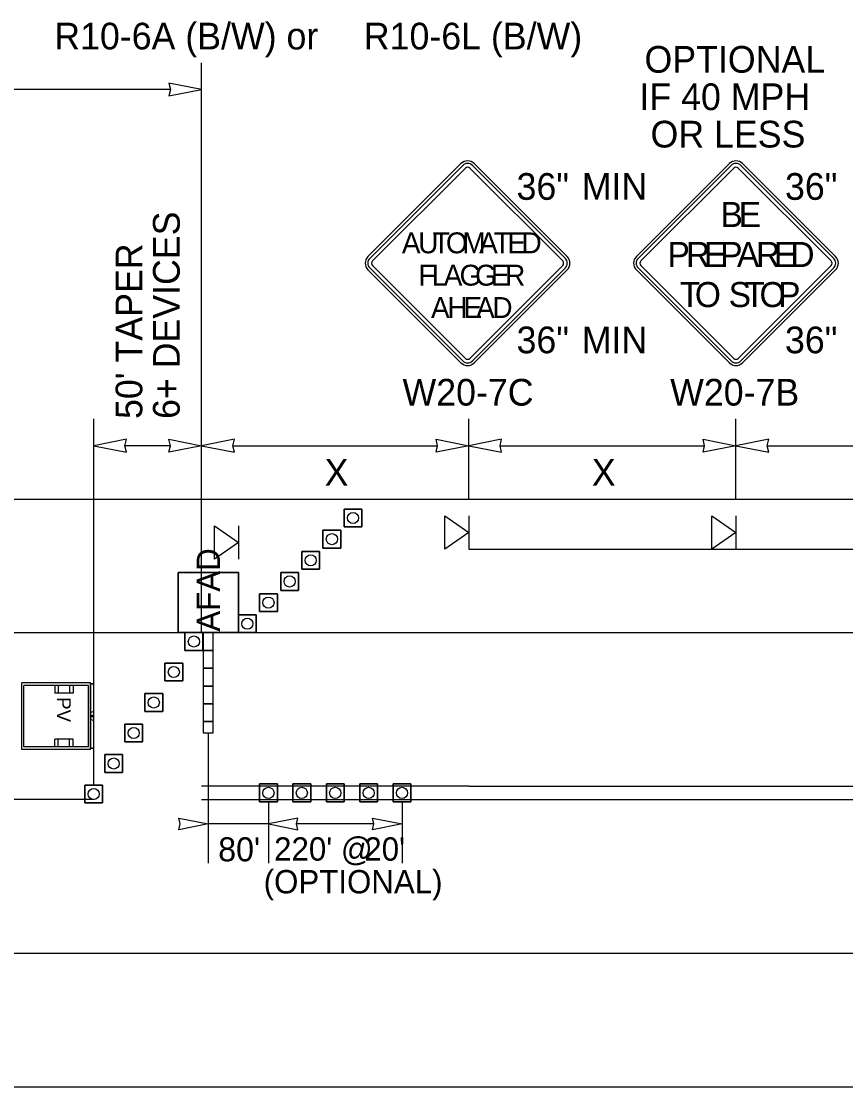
# Model space of a CAD drawing. Extents: x 99999.1 to 100095.7, y 99995 to 100010.7.
# Drawn here: x 100050.933 to 100053.402, y 100005.732 to 100008.923 of the extents above; entities that cross this region are included whole.
import ezdxf

# ---------------------------------------------------------------- set-up
doc = ezdxf.new("R2010")
doc.units = 0
for name, color, linetype in [('RD_ED_ShoulderPavedEdge', 7, 'Continuous'), ('RD_MK_LineDblYellowCenter', 7, 'Continuous'), ('RD_MK_LineEdgeWhite', 7, 'Continuous'), ('RD_MK_LineNoPass', 7, 'Continuous'), ('RD_MK_LineSkipCenter', 7, 'Continuous'), ('TR_SN_ConstructionSigns', 7, 'Continuous'), ('TR_WZ_AFAD', 7, 'Continuous'), ('TR_WZ_PortableSignMountBlk-Org', 7, 'Continuous'), ('TR_WZ_PortableSignMountBlk-Wht', 7, 'Continuous'), ('TR_WZ_ProtectiveVehicle', 7, 'Continuous'), ('TR_WZ_TrafficCone', 7, 'Continuous'), ('TR_WZ_WorkZoneDetails', 7, 'Continuous'), ('TR_WZ_WorkZoneTextCurrent', 7, 'Continuous')]:
    doc.layers.add(name, color=color, linetype=linetype)

msp = doc.modelspace()

# ---------------------------------------------------------------- linework, layer by layer
at = {"layer": 'RD_ED_ShoulderPavedEdge'}
for p, q in [((100040.1076, 100007.4923), (100055.6424, 100007.4923)), ((100040.1076, 100005.7323), (100055.6424, 100005.7323))]:
    msp.add_line(p, q, dxfattribs=at)
at = {"layer": 'RD_MK_LineDblYellowCenter'}
for p, q in [((100052.2733, 100006.6323), (100055.6631, 100006.6323)), ((100052.2733, 100006.5923), (100055.6218, 100006.5923))]:
    msp.add_line(p, q, dxfattribs=at)
at = {"layer": 'RD_MK_LineEdgeWhite'}
for p, q in [((100040.1076, 100007.0923), (100055.6424, 100007.0923)), ((100040.1076, 100006.1323), (100055.6424, 100006.1323))]:
    msp.add_line(p, q, dxfattribs=at)
at = {"layer": 'RD_MK_LineNoPass'}
msp.add_line((100051.4733, 100006.5923), (100052.2733, 100006.5923), dxfattribs=at)
at = {"layer": 'RD_MK_LineSkipCenter'}
for points in [[(100052.2733, 100006.6323), (100051.4733, 100006.6323)], [(100051.15, 100006.5923), (100043.4767, 100006.5923)]]:
    msp.add_lwpolyline(points, dxfattribs=at)
at = {"layer": 'TR_SN_ConstructionSigns'}
for p, q in [((100052.2497, 100008.4972), (100051.9713, 100008.2188)), ((100052.2552, 100008.4917), (100051.9768, 100008.2132)), ((100051.9845, 100008.2055), (100052.263, 100008.4839)), ((100052.2762, 100008.4839), (100052.5546, 100008.2055)), ((100052.5624, 100008.2132), (100052.2839, 100008.4917)), ((100052.5679, 100008.2188), (100052.2895, 100008.4972)), ((100053.0535, 100008.4972), (100052.775, 100008.2188)), ((100053.059, 100008.4917), (100052.7806, 100008.2132)), ((100052.7883, 100008.2055), (100053.0667, 100008.4839)), ((100053.08, 100008.4839), (100053.3584, 100008.2055)), ((100053.3661, 100008.2132), (100053.0877, 100008.4917)), ((100053.3717, 100008.2188), (100053.0932, 100008.4972)), ((100051.9713, 100008.179), (100052.2497, 100007.9006)), ((100051.9768, 100008.1845), (100052.2552, 100007.9061)), ((100052.263, 100007.9138), (100051.9845, 100008.1923)), ((100052.5546, 100008.1923), (100052.2762, 100007.9138)), ((100052.2839, 100007.9061), (100052.5624, 100008.1845)), ((100052.2895, 100007.9006), (100052.5679, 100008.179)), ((100052.775, 100008.179), (100053.0535, 100007.9006)), ((100052.7806, 100008.1845), (100053.059, 100007.9061)), ((100053.0667, 100007.9138), (100052.7883, 100008.1923)), ((100053.3584, 100008.1923), (100053.08, 100007.9138)), ((100053.0877, 100007.9061), (100053.3661, 100008.1845)), ((100053.0932, 100007.9006), (100053.3717, 100008.179))]:
    msp.add_line(p, q, dxfattribs=at)
for centre, radius, start, end in [((100052.2696, 100008.4773), 0.0281, 45, 135), ((100052.2696, 100008.4773), 0.0203, 45, 135), ((100052.2696, 100008.4773), 0.00937, 45, 135), ((100053.0733, 100008.4773), 0.0281, 45, 135), ((100053.0733, 100008.4773), 0.0203, 45, 135), ((100053.0733, 100008.4773), 0.00937, 45, 135), ((100051.9912, 100008.1989), 0.0281, 135, 225), ((100051.9912, 100008.1989), 0.0203, 135, 225), ((100051.9912, 100008.1989), 0.00937, 135, 225), ((100052.548, 100008.1989), 0.00937, 315, 45), ((100052.548, 100008.1989), 0.0203, 315, 45), ((100052.548, 100008.1989), 0.0281, 315, 45), ((100052.7949, 100008.1989), 0.0281, 135, 225), ((100052.7949, 100008.1989), 0.0203, 135, 225), ((100052.7949, 100008.1989), 0.00937, 135, 225), ((100053.3518, 100008.1989), 0.00937, 315, 45), ((100053.3518, 100008.1989), 0.0203, 315, 45), ((100053.3518, 100008.1989), 0.0281, 315, 45), ((100052.2696, 100007.9205), 0.00937, 225, 315), ((100053.0733, 100007.9205), 0.00937, 225, 315), ((100052.2696, 100007.9205), 0.0281, 225, 315), ((100052.2696, 100007.9205), 0.0203, 225, 315), ((100053.0733, 100007.9205), 0.0281, 225, 315), ((100053.0733, 100007.9205), 0.0203, 225, 315)]:
    msp.add_arc(centre, radius, start, end, dxfattribs=at)
at = {"layer": 'TR_WZ_AFAD'}
for p, q in [((100051.4033, 100007.0923), (100051.4033, 100007.2723)), ((100051.4033, 100007.2723), (100051.5833, 100007.2723)), ((100051.5833, 100007.2723), (100051.4033, 100007.2723)), ((100051.4033, 100007.2723), (100051.4033, 100007.0923)), ((100051.5833, 100007.2723), (100051.5833, 100007.0923)), ((100051.5833, 100007.0923), (100051.5833, 100007.2723)), ((100051.5833, 100007.0923), (100051.4033, 100007.0923)), ((100051.5, 100007.0923), (100051.4933, 100007.0923)), ((100051.5, 100007.0923), (100051.5833, 100007.0923)), ((100051.5083, 100007.0923), (100051.5, 100007.0923)), ((100051.5083, 100007.039), (100051.5083, 100007.0923)), ((100051.4783, 100007.039), (100051.4783, 100006.9857)), ((100051.5083, 100006.9857), (100051.5083, 100007.039)), ((100051.4783, 100006.9857), (100051.4783, 100006.9323)), ((100051.4783, 100006.9857), (100051.4933, 100006.9857)), ((100051.4933, 100006.9857), (100051.5083, 100006.9857)), ((100051.5083, 100006.9323), (100051.5083, 100006.9857)), ((100051.4933, 100006.9323), (100051.4783, 100006.9323)), ((100051.4783, 100006.9323), (100051.4783, 100006.879)), ((100051.5083, 100006.9323), (100051.4933, 100006.9323)), ((100051.5083, 100006.879), (100051.5083, 100006.9323)), ((100051.4783, 100006.879), (100051.4783, 100006.8257)), ((100051.4783, 100006.879), (100051.4933, 100006.879)), ((100051.4933, 100006.879), (100051.5083, 100006.879)), ((100051.5083, 100006.8257), (100051.5083, 100006.879)), ((100051.4933, 100006.8257), (100051.4783, 100006.8257)), ((100051.4783, 100006.8257), (100051.4783, 100006.7923)), ((100051.5083, 100006.8257), (100051.4933, 100006.8257))]:
    msp.add_line(p, q, dxfattribs=at)
for points in [[(100051.4033, 100007.0923), (100051.4867, 100007.0923), (100051.5, 100007.0923)], [(100051.4933, 100007.0923), (100051.4867, 100007.0923), (100051.4783, 100007.0923), (100051.4783, 100007.039)], [(100051.4783, 100007.0923), (100051.4783, 100006.7923), (100051.5083, 100006.7923), (100051.5083, 100007.0923)], [(100051.4783, 100007.039), (100051.4933, 100007.039), (100051.5083, 100007.039)], [(100051.5083, 100007.039), (100051.4933, 100007.039), (100051.4783, 100007.039)], [(100051.5083, 100006.9857), (100051.4933, 100006.9857), (100051.4783, 100006.9857)], [(100051.4783, 100006.9323), (100051.4933, 100006.9323), (100051.5083, 100006.9323)], [(100051.5083, 100006.879), (100051.4933, 100006.879), (100051.4783, 100006.879)], [(100051.4783, 100006.8257), (100051.4933, 100006.8257), (100051.5083, 100006.8257)], [(100051.4783, 100006.7923), (100051.5083, 100006.7923), (100051.5083, 100006.8257)]]:
    msp.add_lwpolyline(points, dxfattribs=at)
at = {"layer": 'TR_WZ_PortableSignMountBlk-Org'}
for p, q in [((100052.2733, 100007.4422), (100052.2733, 100007.3422)), ((100053.0733, 100007.4422), (100053.0733, 100007.3422))]:
    msp.add_line(p, q, dxfattribs=at)
for points in [[(100052.2733, 100007.3923), (100052.2015, 100007.3422), (100052.2015, 100007.4422)], [(100053.0733, 100007.3923), (100053.0015, 100007.3422), (100053.0015, 100007.4422)]]:
    msp.add_lwpolyline(points, close=True, dxfattribs=at)
at = {"layer": 'TR_WZ_PortableSignMountBlk-Wht'}
msp.add_line((100051.5833, 100007.4123), (100051.5833, 100007.3123), dxfattribs=at)
msp.add_lwpolyline([(100051.5833, 100007.3624), (100051.5115, 100007.3123), (100051.5115, 100007.4123)], close=True, dxfattribs=at)
at = {"layer": 'TR_WZ_ProtectiveVehicle'}
for p, q in [((100051.1404, 100006.9423), (100050.9347, 100006.9423)), ((100050.9347, 100006.7423), (100050.9347, 100006.9423)), ((100051.1346, 100006.9344), (100050.9405, 100006.9344)), ((100050.9405, 100006.7503), (100050.9405, 100006.9344)), ((100051.0332, 100006.9344), (100051.0332, 100006.9113)), ((100051.0432, 100006.9344), (100051.0432, 100006.9113)), ((100051.0772, 100006.9344), (100051.0772, 100006.9113)), ((100051.0882, 100006.9344), (100051.0882, 100006.9113)), ((100051.1346, 100006.7503), (100051.1346, 100006.9344)), ((100051.1404, 100006.7423), (100051.1404, 100006.9423)), ((100051.1456, 100006.939), (100051.1411, 100006.939)), ((100051.1411, 100006.7456), (100051.1411, 100006.939)), ((100051.15, 100006.7517), (100051.15, 100006.9329)), ((100051.0882, 100006.9113), (100051.0332, 100006.9113)), ((100051.15, 100006.8564), (100051.1411, 100006.8527)), ((100051.15, 100006.8282), (100051.1411, 100006.832)), ((100051.1476, 100006.8423), (100051.1435, 100006.8423)), ((100051.1456, 100006.8395), (100051.1456, 100006.8451)), ((100051.0882, 100006.7733), (100051.0332, 100006.7733)), ((100051.0332, 100006.7503), (100051.0332, 100006.7733)), ((100051.0432, 100006.7503), (100051.0432, 100006.7733)), ((100051.0772, 100006.7503), (100051.0772, 100006.7733)), ((100051.0882, 100006.7503), (100051.0882, 100006.7733)), ((100051.1404, 100006.7423), (100050.9347, 100006.7423)), ((100051.1346, 100006.7503), (100050.9405, 100006.7503)), ((100051.1456, 100006.7456), (100051.1411, 100006.7456))]:
    msp.add_line(p, q, dxfattribs=at)
for centre, major_axis, start_param, end_param in [((100051.1456, 100006.9329), (0, 0.0061), 4.712389, 6.283185), ((100051.1456, 100006.7517), (0, -0.0061), 6.283185, 7.853982)]:
    msp.add_ellipse(centre, major_axis=major_axis, ratio=0.73155, start_param=start_param, end_param=end_param, dxfattribs=at)
msp.add_ellipse((100051.1456, 100006.8423), major_axis=(0, 0.00282), ratio=0.73155, dxfattribs=at)
at = {"layer": 'TR_WZ_TrafficCone'}
for points in [[(100051.9533, 100007.4623), (100051.9, 100007.4623), (100051.9, 100007.409), (100051.9533, 100007.409), (100051.9533, 100007.4623)], [(100051.9533, 100007.409), (100051.9, 100007.409), (100051.9, 100007.4623), (100051.9533, 100007.4623), (100051.9533, 100007.409)], [(100051.89, 100007.399), (100051.8367, 100007.399), (100051.8367, 100007.3457), (100051.89, 100007.3457), (100051.89, 100007.399)], [(100051.89, 100007.3457), (100051.8367, 100007.3457), (100051.8367, 100007.399), (100051.89, 100007.399), (100051.89, 100007.3457)], [(100051.8267, 100007.3357), (100051.7733, 100007.3357), (100051.7733, 100007.2823), (100051.8267, 100007.2823), (100051.8267, 100007.3357)], [(100051.8267, 100007.2823), (100051.7733, 100007.2823), (100051.7733, 100007.3357), (100051.8267, 100007.3357), (100051.8267, 100007.2823)], [(100051.7633, 100007.219), (100051.71, 100007.219), (100051.71, 100007.2723), (100051.7633, 100007.2723), (100051.7633, 100007.219)], [(100051.7633, 100007.2723), (100051.71, 100007.2723), (100051.71, 100007.219), (100051.7633, 100007.219), (100051.7633, 100007.2723)], [(100051.7, 100007.1557), (100051.6467, 100007.1557), (100051.6467, 100007.209), (100051.7, 100007.209), (100051.7, 100007.1557)], [(100051.7, 100007.209), (100051.6467, 100007.209), (100051.6467, 100007.1557), (100051.7, 100007.1557), (100051.7, 100007.209)], [(100051.6367, 100007.0923), (100051.5833, 100007.0923), (100051.5833, 100007.1457), (100051.6367, 100007.1457), (100051.6367, 100007.0923)], [(100051.6367, 100007.1457), (100051.5833, 100007.1457), (100051.5833, 100007.0923), (100051.6367, 100007.0923), (100051.6367, 100007.1457)], [(100051.4766, 100007.0923), (100051.4233, 100007.0923), (100051.4233, 100007.039), (100051.4766, 100007.039), (100051.4766, 100007.0923)], [(100051.4766, 100007.039), (100051.4233, 100007.039), (100051.4233, 100007.0923), (100051.4766, 100007.0923), (100051.4766, 100007.039)], [(100051.4166, 100007.001), (100051.3633, 100007.001), (100051.3633, 100006.9477), (100051.4166, 100006.9477), (100051.4166, 100007.001)], [(100051.4166, 100006.9477), (100051.3633, 100006.9477), (100051.3633, 100007.001), (100051.4166, 100007.001), (100051.4166, 100006.9477)], [(100051.3566, 100006.9097), (100051.3033, 100006.9097), (100051.3033, 100006.8563), (100051.3566, 100006.8563), (100051.3566, 100006.9097)], [(100051.3566, 100006.8563), (100051.3033, 100006.8563), (100051.3033, 100006.9097), (100051.3566, 100006.9097), (100051.3566, 100006.8563)], [(100051.2966, 100006.8183), (100051.2433, 100006.8183), (100051.2433, 100006.765), (100051.2966, 100006.765), (100051.2966, 100006.8183)], [(100051.2966, 100006.765), (100051.2433, 100006.765), (100051.2433, 100006.8183), (100051.2966, 100006.8183), (100051.2966, 100006.765)], [(100051.2366, 100006.727), (100051.1833, 100006.727), (100051.1833, 100006.6737), (100051.2366, 100006.6737), (100051.2366, 100006.727)], [(100051.2366, 100006.6737), (100051.1833, 100006.6737), (100051.1833, 100006.727), (100051.2366, 100006.727), (100051.2366, 100006.6737)], [(100051.1766, 100006.6357), (100051.1233, 100006.6357), (100051.1233, 100006.5823), (100051.1766, 100006.5823), (100051.1766, 100006.6357)], [(100051.1766, 100006.5823), (100051.1233, 100006.5823), (100051.1233, 100006.6357), (100051.1766, 100006.6357), (100051.1766, 100006.5823)], [(100051.7, 100006.639), (100051.6467, 100006.639), (100051.6467, 100006.5857), (100051.7, 100006.5857), (100051.7, 100006.639)], [(100051.7, 100006.5857), (100051.6467, 100006.5857), (100051.6467, 100006.639), (100051.7, 100006.639), (100051.7, 100006.5857)], [(100051.8, 100006.639), (100051.7467, 100006.639), (100051.7467, 100006.5857), (100051.8, 100006.5857), (100051.8, 100006.639)], [(100051.8, 100006.5857), (100051.7467, 100006.5857), (100051.7467, 100006.639), (100051.8, 100006.639), (100051.8, 100006.5857)], [(100051.9, 100006.639), (100051.8467, 100006.639), (100051.8467, 100006.5857), (100051.9, 100006.5857), (100051.9, 100006.639)], [(100051.9, 100006.5857), (100051.8467, 100006.5857), (100051.8467, 100006.639), (100051.9, 100006.639), (100051.9, 100006.5857)], [(100052, 100006.639), (100051.9467, 100006.639), (100051.9467, 100006.5857), (100052, 100006.5857), (100052, 100006.639)], [(100052, 100006.5857), (100051.9467, 100006.5857), (100051.9467, 100006.639), (100052, 100006.639), (100052, 100006.5857)], [(100052.1, 100006.639), (100052.0467, 100006.639), (100052.0467, 100006.5857), (100052.1, 100006.5857), (100052.1, 100006.639)], [(100052.1, 100006.5857), (100052.0467, 100006.5857), (100052.0467, 100006.639), (100052.1, 100006.639), (100052.1, 100006.5857)]]:
    msp.add_lwpolyline(points, dxfattribs=at)
for centre in [(100051.9267, 100007.4357), (100051.8633, 100007.3723), (100051.8, 100007.309), (100051.7367, 100007.2457), (100051.6733, 100007.1823), (100051.61, 100007.119), (100051.45, 100007.0657), (100051.39, 100006.9743), (100051.33, 100006.883), (100051.27, 100006.7917), (100051.21, 100006.7003), (100051.15, 100006.609), (100051.6733, 100006.6123), (100051.7733, 100006.6123), (100051.8733, 100006.6123), (100051.9733, 100006.6123), (100052.0733, 100006.6123)]:
    msp.add_circle(centre, 0.0167, dxfattribs=at)
at = {"layer": 'TR_WZ_WorkZoneDetails'}
for p, q in [((100051.4733, 100007.0923), (100051.4733, 100008.7991)), ((100051.3796, 100008.7191), (100044.3704, 100008.7191)), ((100051.15, 100006.6357), (100051.15, 100007.7323)), ((100052.2733, 100007.4923), (100052.2733, 100007.7323)), ((100053.0733, 100007.4923), (100053.0733, 100007.7323)), ((100051.3796, 100007.6523), (100051.2437, 100007.6523)), ((100051.5671, 100007.6523), (100052.1796, 100007.6523)), ((100052.3671, 100007.6523), (100052.9796, 100007.6523)), ((100053.1671, 100007.6523), (100053.7796, 100007.6523)), ((100052.2733, 100007.3422), (100054.6733, 100007.3422)), ((100051.4933, 100006.7923), (100051.4933, 100006.4023)), ((100051.6733, 100006.5857), (100051.6733, 100006.4023)), ((100052.0733, 100006.5857), (100052.0733, 100006.4023)), ((100051.6733, 100006.5193), (100051.4933, 100006.5193)), ((100051.989, 100006.5193), (100051.7577, 100006.5193))]:
    msp.add_line(p, q, dxfattribs=at)
for points in [[(100051.4733, 100008.7191), (100051.3751, 100008.7384), (100051.3796, 100008.7191), (100051.3751, 100008.6998)], [(100051.15, 100007.6523), (100051.2483, 100007.6331), (100051.2437, 100007.6523), (100051.2483, 100007.6716)], [(100051.4733, 100007.6523), (100051.3751, 100007.6331), (100051.3796, 100007.6523), (100051.3751, 100007.6716)], [(100051.4733, 100007.6523), (100051.5716, 100007.6331), (100051.5671, 100007.6523), (100051.5716, 100007.6716)], [(100052.2733, 100007.6523), (100052.1751, 100007.6331), (100052.1796, 100007.6523), (100052.1751, 100007.6716)], [(100052.2733, 100007.6523), (100052.3716, 100007.6331), (100052.3671, 100007.6523), (100052.3716, 100007.6716)], [(100053.0733, 100007.6523), (100052.9751, 100007.6331), (100052.9796, 100007.6523), (100052.9751, 100007.6716)], [(100053.0733, 100007.6523), (100053.1716, 100007.6331), (100053.1671, 100007.6523), (100053.1716, 100007.6716)], [(100051.4933, 100006.5193), (100051.4049, 100006.502), (100051.409, 100006.5193), (100051.4049, 100006.5367)], [(100051.6733, 100006.5193), (100051.7618, 100006.502), (100051.7577, 100006.5193), (100051.7618, 100006.5367)], [(100052.0733, 100006.5193), (100051.9849, 100006.502), (100051.989, 100006.5193), (100051.9849, 100006.5367)]]:
    msp.add_lwpolyline(points, close=True, dxfattribs=at)

# ---------------------------------------------------------------- texts
at = {"layer": 'TR_SN_ConstructionSigns'}
for s, p in [('R10-6A (B/W) or', (100051.032, 100008.8391)), ('R10-6L (B/W)', (100051.959, 100008.8391)), ('36"', (100052.4163, 100008.3887)), ('MIN', (100052.6114, 100008.3887)), ('36"', (100053.2201, 100008.3887)), ('36"', (100052.4163, 100007.9291)), ('MIN', (100052.6114, 100007.9291)), ('36"', (100053.2201, 100007.9291)), ('W20-7C', (100052.0748, 100007.7723)), ('W20-7B', (100052.8763, 100007.7723))]:
    msp.add_text(s, height=0.08, rotation=360, dxfattribs=at).set_placement(p)
for s, height, p in [('OPTIONAL', 0.08, (100052.7994, 100008.7694)), ('IF 40 MPH', 0.08, (100052.7843, 100008.6574)), ('OR LESS', 0.08, (100052.8175, 100008.5454)), ('B', 0.075, (100053.0271, 100008.3074)), ('E', 0.075, (100053.0814, 100008.3074)), ('A', 0.0625, (100052.073, 100008.2286)), ('U', 0.0625, (100052.1218, 100008.2286)), ('T', 0.0625, (100052.1655, 100008.2286)), ('O', 0.0625, (100052.2049, 100008.2286)), ('M', 0.0625, (100052.2543, 100008.2286)), ('A', 0.0625, (100052.3043, 100008.2286)), ('T', 0.0625, (100052.348, 100008.2286)), ('E', 0.0625, (100052.3886, 100008.2286)), ('D', 0.0625, (100052.4311, 100008.2286)), ('P', 0.075, (100052.8684, 100008.1874)), ('R', 0.075, (100052.9237, 100008.1874)), ('E', 0.075, (100052.9769, 100008.1874)), ('P', 0.075, (100053.0264, 100008.1874)), ('A', 0.075, (100053.0763, 100008.1874)), ('R', 0.075, (100053.1335, 100008.1874)), ('E', 0.075, (100053.1868, 100008.1874)), ('D', 0.075, (100053.2362, 100008.1874)), ('F', 0.0625, (100052.1221, 100008.1317)), ('L', 0.0625, (100052.1627, 100008.1317)), ('A', 0.0625, (100052.1983, 100008.1317)), ('G', 0.0625, (100052.2458, 100008.1317)), ('G', 0.0625, (100052.2921, 100008.1317)), ('E', 0.0625, (100052.3396, 100008.1317)), ('R', 0.0625, (100052.3821, 100008.1317)), ('T', 0.075, (100052.9051, 100008.0674)), ('O', 0.075, (100052.9502, 100008.0674)), ('S', 0.075, (100053.0516, 100008.0674)), ('T', 0.075, (100053.0988, 100008.0674)), ('O', 0.075, (100053.1439, 100008.0674)), ('P', 0.075, (100053.1996, 100008.0674)), ('A', 0.0625, (100052.1602, 100008.0348)), ('H', 0.0625, (100052.209, 100008.0348)), ('E', 0.0625, (100052.2577, 100008.0348)), ('A', 0.0625, (100052.2952, 100008.0348)), ('D', 0.0625, (100052.344, 100008.0348))]:
    msp.add_text(s, height=height, dxfattribs=at).set_placement(p)
at = {"layer": 'TR_WZ_AFAD'}
msp.add_text('AFAD', height=0.07, rotation=90, dxfattribs=at).set_placement((100051.5283, 100007.0953))
at = {"layer": 'TR_WZ_ProtectiveVehicle'}
msp.add_text('PV', height=0.04175, rotation=270, dxfattribs=at).set_placement((100051.0398, 100006.899))
at = {"layer": 'TR_WZ_WorkZoneTextCurrent'}
for s, p in [('6+ DEVICES', (100051.4077, 100007.7323)), ("50' TAPER", (100051.2957, 100007.7323))]:
    msp.add_text(s, height=0.08, rotation=90, dxfattribs=at).set_placement(p)
for s, height, p in [('X', 0.08, (100051.8416, 100007.5323)), ('X', 0.08, (100052.6416, 100007.5323)), ("80'", 0.072, (100051.5229, 100006.4073)), ("220' @", 0.07, (100051.6903, 100006.4093)), ("20'", 0.07, (100051.9604, 100006.4093)), ('(OPTIONAL)', 0.07, (100051.659, 100006.3113))]:
    msp.add_text(s, height=height, dxfattribs=at).set_placement(p)

doc.saveas('drawing.dxf')
